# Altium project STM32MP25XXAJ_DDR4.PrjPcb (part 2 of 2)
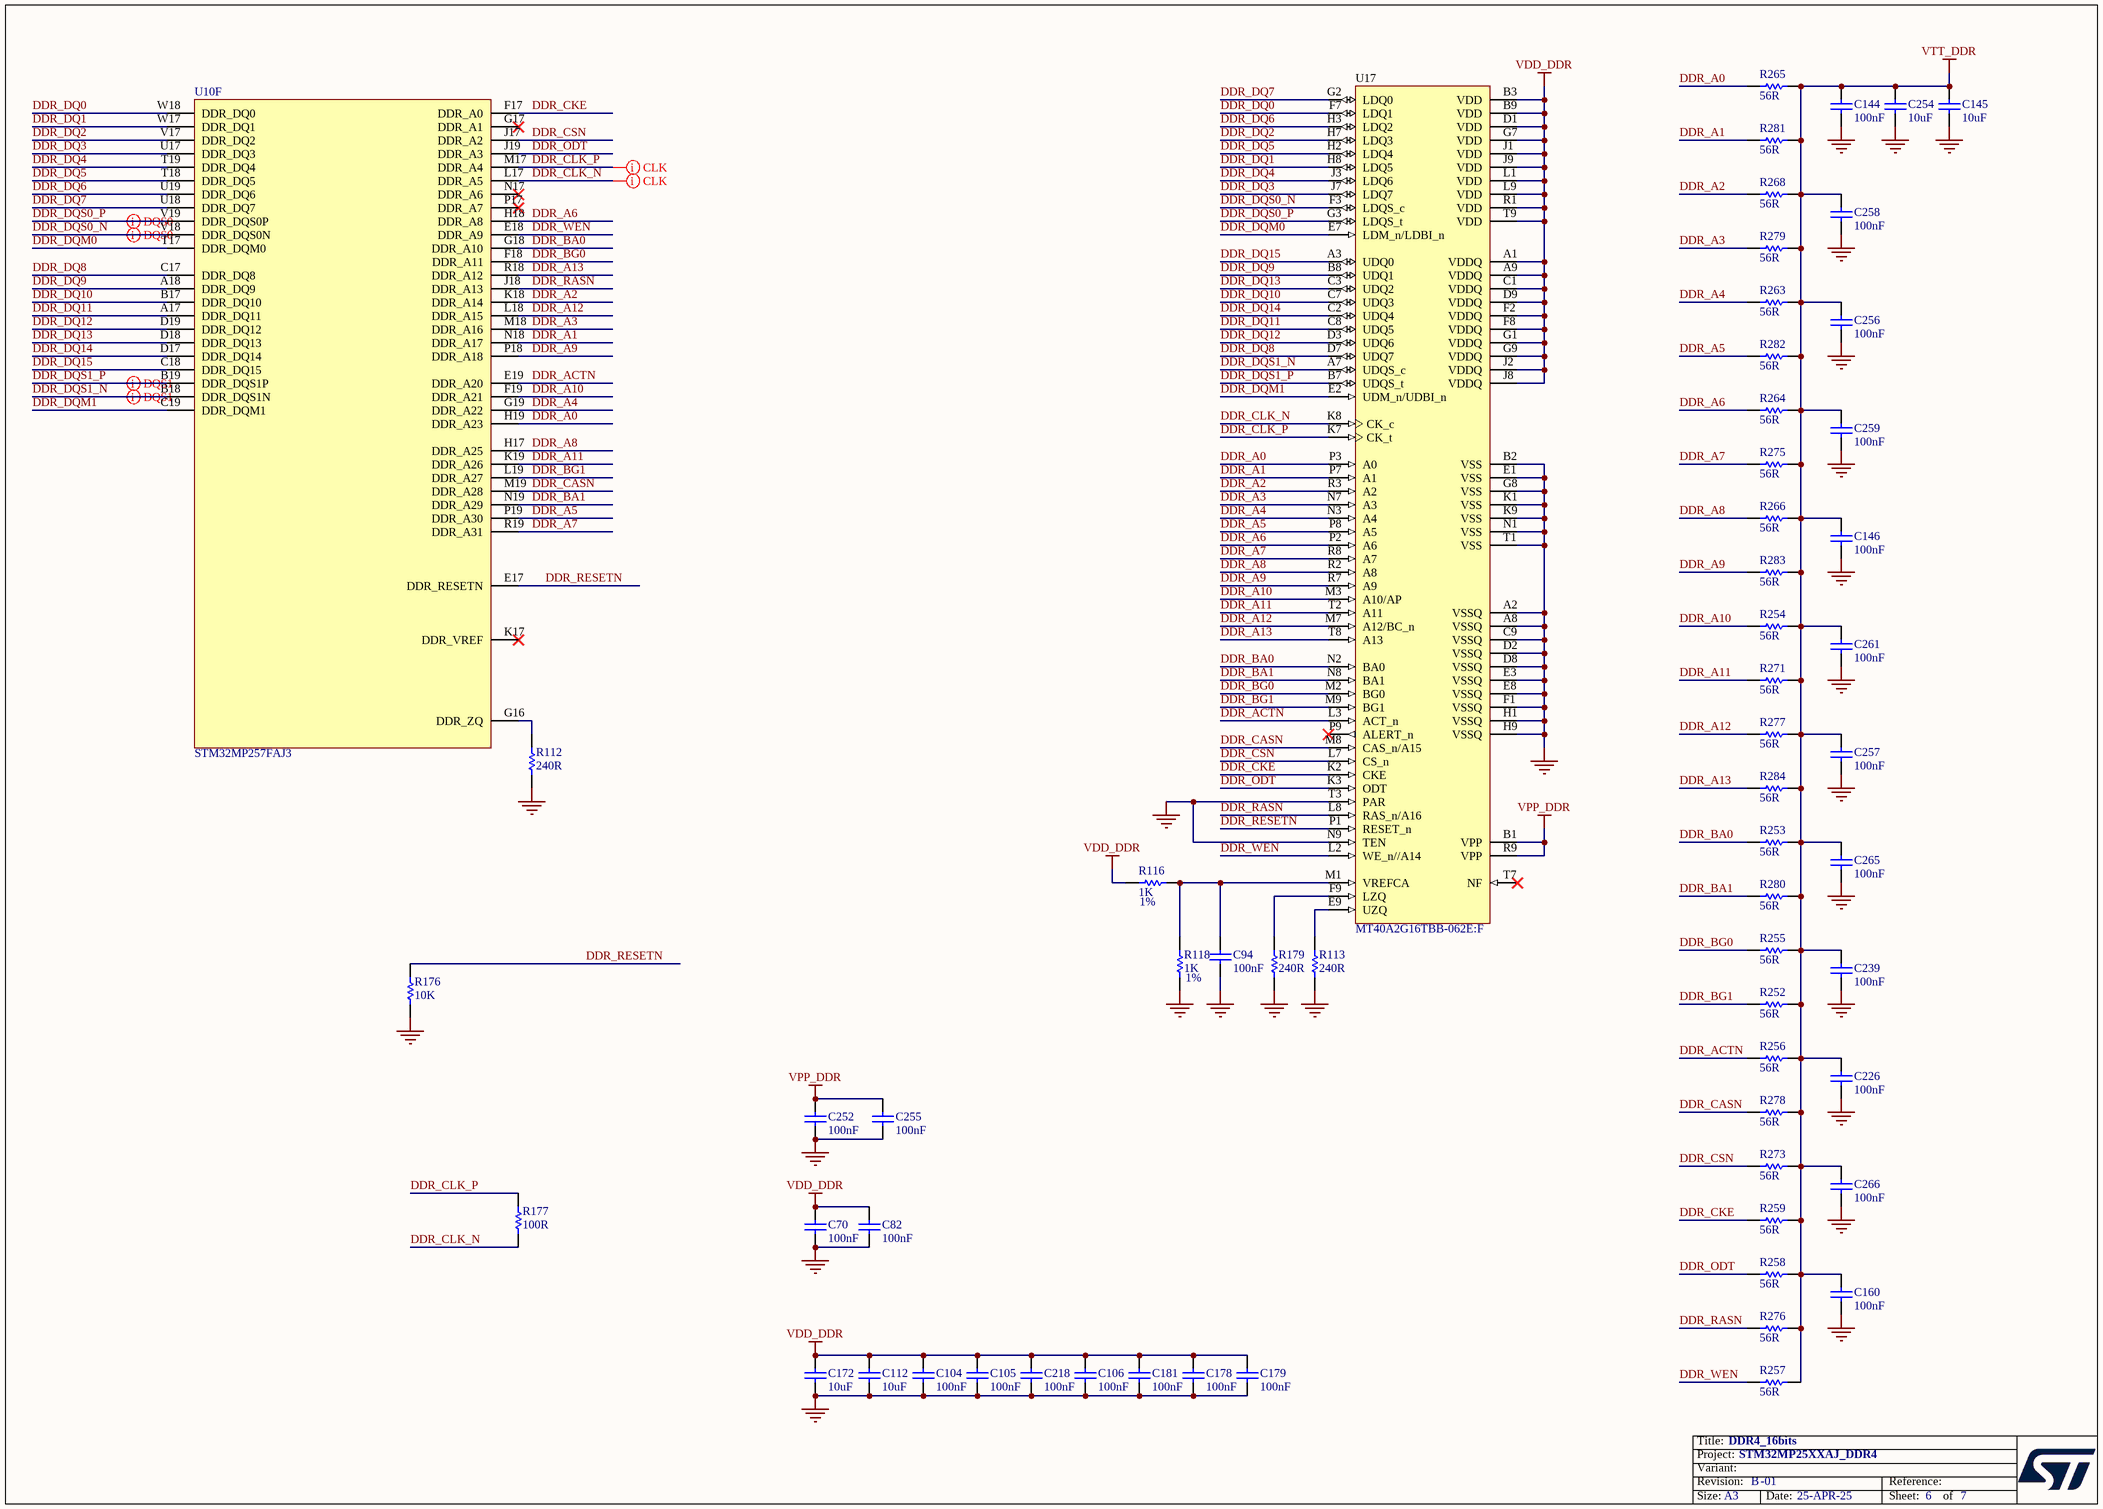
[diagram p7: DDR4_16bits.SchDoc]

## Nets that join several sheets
1V8: PMIC (5 pins), STM32MP25XXAJ Power (24 pins), eMMC (11 pins)
GND: STM32MP25XXAJ I_Os (10 pins), PMIC (62 pins), STM32MP25XXAJ Power (97 pins), eMMC (17 pins), DDR4_16bits (52 pins)
VDD3V3_USB: PMIC (C156.2 U26.13), STM32MP25XXAJ Power (R197.1)
VDD_DDR: PMIC (7 pins), STM32MP25XXAJ Power (16 pins), DDR4_16bits (32 pins)
VDD_EMMC: PMIC (C190.1 U26.16), eMMC (6 pins)
VDDA1V8_AON: STM32MP25XXAJ I_Os (U10.P1), PMIC (C189.2 U26.14), STM32MP25XXAJ Power (C393.2 U10.M6)
VDDCORE: PMIC (6 pins), STM32MP25XXAJ Power (23 pins)
VDDCPU: PMIC (5 pins), STM32MP25XXAJ Power (10 pins)
VDDGPU: PMIC (6 pins), STM32MP25XXAJ Power (10 pins)
VDDIO: STM32MP25XXAJ I_Os (R27.2 R260.2 R261.2), PMIC (6 pins), STM32MP25XXAJ Power (17 pins)
VDDIO_SDCARD: PMIC (C217.1 U26.2), STM32MP25XXAJ Power (C357.2 U10.F14)
VPP_DDR: PMIC (C91.1 U26.7), DDR4_16bits (C252.2 C255.2 U17.B1 U17.R9)
VTT_DDR: PMIC (C40.2 U26.44), DDR4_16bits (39 pins)
eMMC.SDMMC2_CK: STM32MP25XXAJ I_Os (U10.F15), eMMC (R49.1 U24.M6)
eMMC.SDMMC2_CMD: STM32MP25XXAJ I_Os (U10.F16), eMMC (R37.1 U24.M5)
eMMC.SDMMC2_D0: STM32MP25XXAJ I_Os (U10.E15), eMMC (R44.1 U24.A3)
eMMC.SDMMC2_D1: STM32MP25XXAJ I_Os (U10.A15), eMMC (U24.A4)
eMMC.SDMMC2_D2: STM32MP25XXAJ I_Os (U10.C14), eMMC (U24.A5)
eMMC.SDMMC2_D3: STM32MP25XXAJ I_Os (U10.D15), eMMC (U24.B2)
eMMC.SDMMC2_D4: STM32MP25XXAJ I_Os (U10.E14), eMMC (U24.B3)
eMMC.SDMMC2_D5: STM32MP25XXAJ I_Os (U10.B15), eMMC (U24.B4)
eMMC.SDMMC2_D6: STM32MP25XXAJ I_Os (U10.A14), eMMC (U24.B5)
eMMC.SDMMC2_D7: STM32MP25XXAJ I_Os (U10.B14), eMMC (U24.B6)
I2C7.SCL: STM32MP25XXAJ I_Os (R261.1 U10.B12), PMIC (U26.33)
I2C7.SDA: STM32MP25XXAJ I_Os (R260.1 U10.D12), PMIC (U26.34)
MP257_WAKEUP: STM32MP25XXAJ I_Os (U10.P5), PMIC (U26.32)
NRST: STM32MP25XXAJ I_Os (C33.2 U10.N1), PMIC (R81.1)
NRSTC1MS: STM32MP25XXAJ I_Os (R27.1 R272.1 U10.P2), PMIC (R59.1), eMMC (D5.2)
PMIC_WAKEUPn: STM32MP25XXAJ I_Os (U10.K5), PMIC (R46.1)
PWR_CPU_ON: STM32MP25XXAJ I_Os (R272.2 U10.N2), PMIC (R60.1)
PWR_ON: STM32MP25XXAJ I_Os (U10.P3), PMIC (R2.1)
